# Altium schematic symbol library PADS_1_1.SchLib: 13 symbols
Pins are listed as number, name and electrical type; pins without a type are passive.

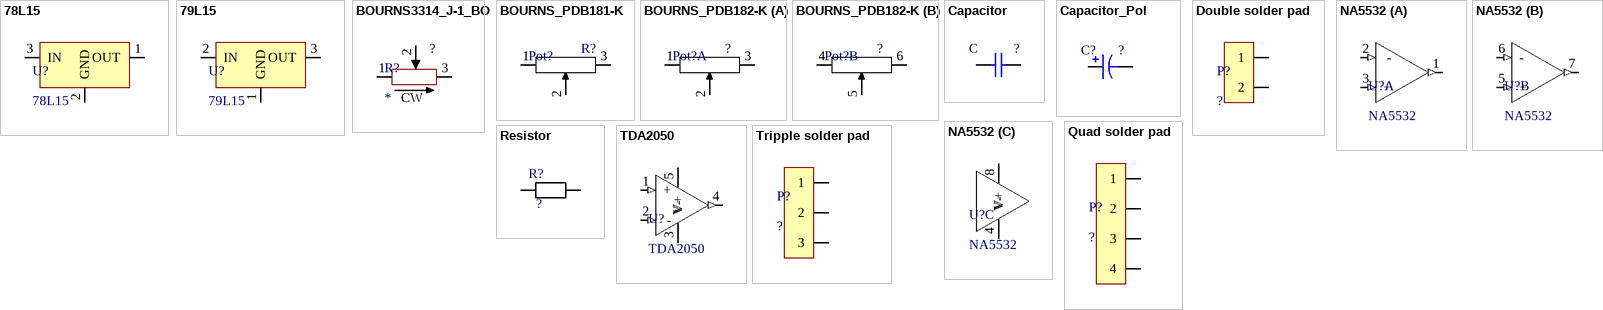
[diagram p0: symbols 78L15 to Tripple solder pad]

## 78L15
designator U?
footprint TO-92_BO
footprint SOT89
pins: 1 OUT, 2 GND, 3 IN

## 79L15
designator U?
footprint TO-92_BO
footprint SOT89
pins: 1 GND, 2 IN, 3 OUT

## BOURNS3314_J-1_BO
designator R?
footprint BOURNS_J-1_BO
pins: 1, 2, 3

## BOURNS_PDB181-K
designator Pot?  (value not drawn)
footprint PDB181-K_BO
pins: 1, 2, 3

## BOURNS_PDB182-K
designator Pot?, comment ?
footprint PDB182-K_BO
part A pins: 1, 2, 3
part B pins: 4, 5, 6

## Capacitor
designator C  (value not drawn)
footprint CAP_MKT_2.5x6.5x7.2 (Raster 5)
footprint CAP_MKT_5x10x7.2 (Raster 5)
footprint CAP_MKT_3.5x8.5x7.2 (Raster 5)
footprint CAP_MLCC (Raster 5)
footprint CAP_MKT_3x7.5x7.2 (Raster 5)
footprint CAP SMD 1x0.5x0.5
footprint CAP SMD 1.6x0.8x0.8
footprint CAP SMD 2x1.25x1.25
footprint CAP SMD 3.2x1.6x1.6
pins: 1, 2

## Capacitor_Pol
designator C?  (value not drawn)
footprint Panasonic_K16_BO
footprint CAP_POL_s16x25 (Raster 7.5)
footprint CAP_POL_s10x20 (Raster 5)
footprint CAP_POL_s10x16 (Raster 5)
footprint CAP_POL_s6.3x11 (Raster 2.5)
footprint CAP_POL_s5x11 (Raster 2)
footprint CAP_POL_SMD_8.5x8.5x10.7
footprint CAP_POL_SMD_6.8x6.8x8
footprint CAP_POL_SMD_6.8x6.8x6
footprint CAP_POL_SMD_4.5x4.5x6
pins: 1, 2

## Double solder pad
designator P?, comment ?
footprint double solder pad
pins: 1, 2

## NA5532
designator U?
footprint DIP8_BO
footprint SOT96-1
part A pins: 1 (out), 2  - (in), 3 + (in)
part B pins: 5 + (in), 6 - (in), 7 (out)
part C pins: 4 V- (power), 8 V+ (power)

## Quad solder pad
designator P?, comment ?
footprint quad solder pad
pins: 1, 2, 3, 4

## Resistor
designator R?  (value not drawn)
footprint RES (Raster 10mm)
footprint RES_SMD_3.1x1.6x0.6
pins: 1 OUT, 2 OUT

## TDA2050
designator U?
footprint TO-22B_BO
pins: 1 + (in), 2  - (in), 3 V- (power), 4 (out), 5 V+ (power)

## Tripple solder pad
designator P?, comment ?
footprint tripple solder pad
pins: 1, 2, 3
